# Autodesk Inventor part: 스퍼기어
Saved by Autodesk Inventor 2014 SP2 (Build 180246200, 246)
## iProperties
Created: 2024-04
Part Number: 스퍼기어
Material: Generic
Document SubType Name: Modeling
Designer: Administrator
Density: 1 g/cm^3
Appearance: Default
Author: Administrator
Author: jhkim
Creation Date: 2024-04-08
Sending System: Autodesk Inventor 2025
Preprocessor: ST-DEVELOPER v20
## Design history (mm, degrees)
node "스퍼기어1"
node "솔리드1"
node "기준1"
